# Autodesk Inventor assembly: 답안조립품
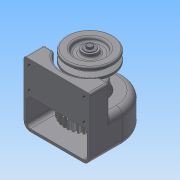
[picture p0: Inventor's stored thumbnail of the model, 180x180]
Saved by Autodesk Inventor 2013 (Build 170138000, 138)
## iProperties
Created: 2015-02
Part Number: 답안조립품
Document SubType Name: Assembly
Designer: Administrator
Author: Administrator
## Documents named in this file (14)
- C:\Documents and Settings\Administrator\바탕 화면\450214V1024\답안조립품.iam
- C:\Documents and Settings\Administrator\바탕 화면\450214V1024\본체.ipt
- C:\Documents and Settings\Administrator\바탕 화면\450214V1024\베어링 6001.ipt
- C:\Documents and Settings\Administrator\바탕 화면\450214V1024\축.ipt
- C:\Documents and Settings\Administrator\바탕 화면\450214V1024\축커버.ipt
- C:\Documents and Settings\Administrator\바탕 화면\450214V1024\M3x0.5.ipt
- C:\Documents and Settings\Administrator\바탕 화면\450214V1024\오일실.ipt
- C:\Documents and Settings\Administrator\바탕 화면\450214V1024\V-벨트풀리.ipt
- C:\Documents and Settings\Administrator\바탕 화면\450214V1024\키4x4.ipt
- C:\Documents and Settings\Administrator\바탕 화면\450214V1024\와샤.ipt
- C:\Documents and Settings\Administrator\바탕 화면\450214V1024\M5x0.8.ipt
- M5x0.8.ipt
- C:\Documents and Settings\Administrator\바탕 화면\450214V1024\키5x5.ipt
- C:\Documents and Settings\Administrator\바탕 화면\450214V1024\스퍼기어.ipt
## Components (6 placed, 3 different names)
1. V-벨트풀리:1 — 플러쉬:1, 각도:2
2. M5x0.8:1 — 각도:3
3. M3x0.5:1
4. M3x0.5:2
5. M3x0.5:3
6. M3x0.5:4
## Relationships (3: Angle 2, Flush 1)
- 플러쉬:1 [Flush]: V-벨트풀리:1
- 각도:2 [Angle]: V-벨트풀리:1
- 각도:3 [Angle]: M5x0.8:1
